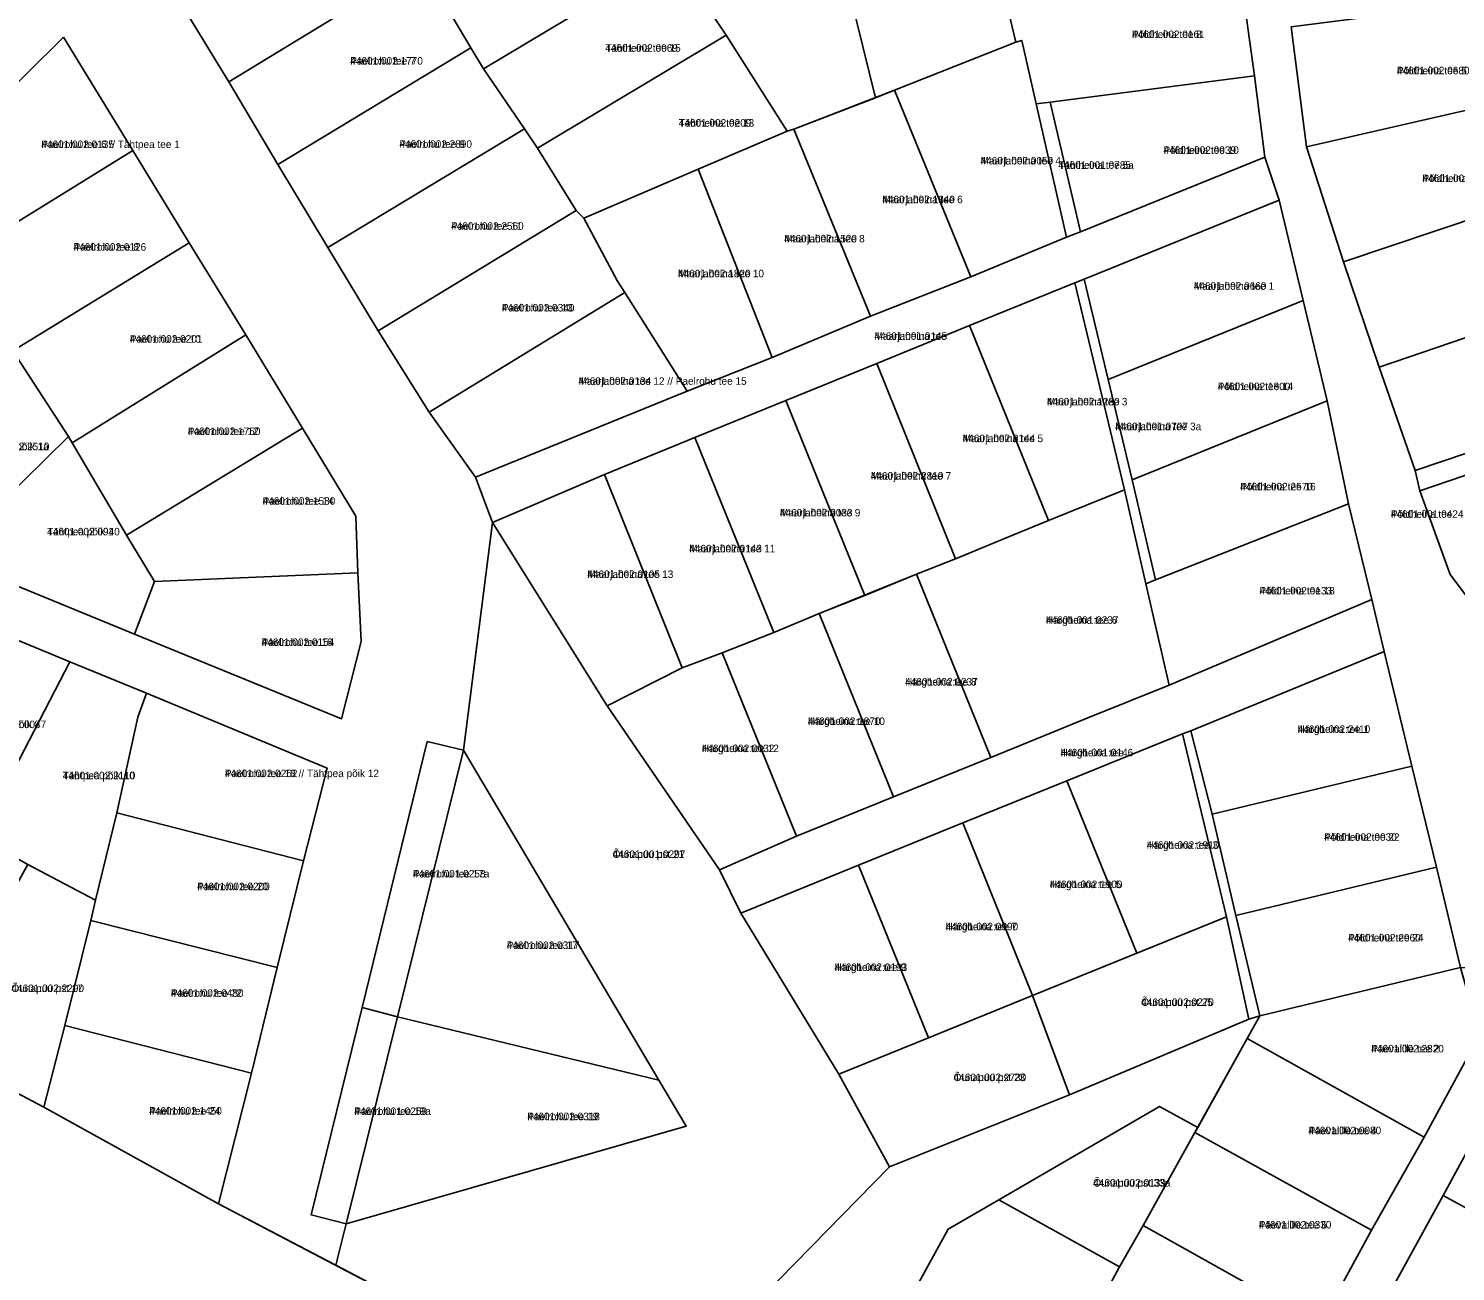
# Model space of a CAD drawing. Extents: x 551843 to 558501, y 6589003 to 6595718.
# Drawn here: x 552375.1 to 552659.9, y 6593483.8 to 6593731.8 of the extents above; entities that cross this region are included whole.
import ezdxf

# ---------------------------------------------------------------- set-up
doc = ezdxf.new("R2010")
doc.units = 0
for name, color, linetype in [('L_AADRESS', 7, 'Continuous'), ('PIIR', 7, 'Continuous'), ('TUNNUS', 7, 'Continuous')]:
    doc.layers.add(name, color=color, linetype=linetype)

msp = doc.modelspace()

# ---------------------------------------------------------------- linework, layer by layer
at = {"layer": 'PIIR'}
for points in [[(552493.73, 6593763), (552503.69, 6593746.35), (552465.93, 6593723.75), (552463.36, 6593727.89), (552455.97, 6593740.4)], [(552415.05, 6593721.12), (552404.98, 6593737.65), (552443.41, 6593761.06), (552446.01, 6593757.04), (552453.48, 6593744.53)], [(552544.13, 6593717.92), (552536.52, 6593748.99), (552565.77, 6593756.12), (552565.86, 6593755.74), (552570.38, 6593736.55), (552572.15, 6593729.03), (552547.97, 6593719.47)], [(552424.83, 6593704.63), (552415.05, 6593721.12), (552453.48, 6593744.53), (552455.97, 6593740.4), (552463.36, 6593727.89)], [(552503.69, 6593746.35), (552514.35, 6593730.44), (552476.69, 6593707.93), (552474.09, 6593711.76), (552465.93, 6593723.75)], [(552572.15, 6593729.03), (552570.38, 6593736.55), (552574.46, 6593737.11), (552616.94, 6593742.99), (552619.81, 6593722.34), (552579.05, 6593717.11), (552576.21, 6593716.75), (552573.34, 6593729.4)], [(552627.12, 6593732.09), (552666.3, 6593737.11), (552668.87, 6593717.03), (552630.18, 6593708.17)], [(552382.03, 6593730.06), (552351.96, 6593700.34), (552354.8, 6593695.88), (552337.85, 6593679.4), (552323.89, 6593665.69), (552305.25, 6593647.4), (552336.12, 6593634.77), (552358.56, 6593626.36), (552396.25, 6593610.93), (552437.54, 6593594.04), (552441.45, 6593609.45), (552440.81, 6593623.15), (552440.38, 6593634.5), (552429.75, 6593652.06), (552418.45, 6593670.64), (552407.17, 6593689.04), (552395.89, 6593707.45)], [(552382.03, 6593730.06), (552395.89, 6593707.45), (552360.87, 6593685.8), (552354.8, 6593695.88), (552351.96, 6593700.34)], [(552476.69, 6593707.93), (552514.35, 6593730.44), (552526.5, 6593711.28), (552508.72, 6593703.69), (552485.91, 6593693.95), (552484.41, 6593695.45)], [(552434.84, 6593688.06), (552424.83, 6593704.63), (552463.36, 6593727.89), (552465.93, 6593723.75), (552474.09, 6593711.76)], [(552573.34, 6593729.4), (552576.07, 6593717.35), (552576.21, 6593716.75), (552582.28, 6593690.17), (552563.19, 6593682.26), (552547.97, 6593719.47), (552572.15, 6593729.03)], [(552619.81, 6593722.34), (552621.88, 6593706.11), (552585.09, 6593691.2), (552579.05, 6593717.11)], [(552543.16, 6593674.39), (552527.83, 6593711.71), (552547.97, 6593719.47), (552563.19, 6593682.26)], [(552576.21, 6593716.75), (552579.05, 6593717.11), (552585.09, 6593691.2), (552582.28, 6593690.17)], [(552630.18, 6593708.17), (552668.87, 6593717.03), (552675.27, 6593697.83), (552637.59, 6593685.25)], [(552444.84, 6593671.49), (552434.84, 6593688.06), (552474.09, 6593711.76), (552476.69, 6593707.93), (552484.41, 6593695.45)], [(552543.16, 6593674.39), (552523.53, 6593666.14), (552508.72, 6593703.69), (552526.5, 6593711.28), (552527.83, 6593711.71)], [(552407.17, 6593689.04), (552371.96, 6593667.45), (552371.01, 6593668.92), (552360.87, 6593685.8), (552395.89, 6593707.45)], [(552467.7, 6593633.22), (552464.3, 6593642.26), (552506.56, 6593659.39), (552523.53, 6593666.14), (552543.16, 6593674.39), (552563.19, 6593682.26), (552582.28, 6593690.17), (552585.09, 6593691.2), (552621.88, 6593706.11), (552624.76, 6593697.55), (552585.83, 6593681.78), (552583.95, 6593681.02), (552562.94, 6593672.52), (552544.4, 6593664.92), (552526.25, 6593657.56), (552508.11, 6593650.2), (552490.05, 6593642.82)], [(552506.56, 6593659.39), (552494.11, 6593679.11), (552492.67, 6593681.34), (552485.91, 6593693.95), (552508.72, 6593703.69), (552523.53, 6593666.14)], [(552624.76, 6593697.55), (552629.55, 6593677.52), (552590.61, 6593661.75), (552585.83, 6593681.78)], [(552644.69, 6593664.18), (552637.59, 6593685.25), (552675.27, 6593697.83), (552682.36, 6593677.03)], [(552484.41, 6593695.45), (552485.91, 6593693.95), (552492.67, 6593681.34), (552494.11, 6593679.11), (552455.04, 6593655.2), (552444.84, 6593671.49)], [(552407.17, 6593689.04), (552418.45, 6593670.64), (552383.81, 6593649.14), (552383.03, 6593650.38), (552371.96, 6593667.45)], [(552590.61, 6593661.75), (552595.4, 6593641.72), (552600.06, 6593621.77), (552598.13, 6593621.01), (552593.83, 6593639.72), (552583.95, 6593681.02), (552585.83, 6593681.78)], [(552494.11, 6593679.11), (552506.56, 6593659.39), (552464.3, 6593642.26), (552455.04, 6593655.2)], [(552583.95, 6593681.02), (552593.83, 6593639.72), (552578.71, 6593633.59), (552562.94, 6593672.52)], [(552590.61, 6593661.75), (552629.55, 6593677.52), (552634.33, 6593657.49), (552595.4, 6593641.72)], [(552651.9, 6593643.62), (552644.69, 6593664.18), (552682.36, 6593677.03), (552689.32, 6593656.23)], [(552429.75, 6593652.06), (552394.61, 6593630.69), (552383.81, 6593649.14), (552418.45, 6593670.64)], [(552562.94, 6593672.52), (552578.71, 6593633.59), (552571.71, 6593630.76), (552560.15, 6593625.97), (552544.4, 6593664.92)], [(552383.03, 6593650.38), (552364.9, 6593632.58), (552358.56, 6593626.36), (552336.12, 6593634.77), (552345.56, 6593644.05), (552359.64, 6593657.88), (552371.01, 6593668.92), (552371.96, 6593667.45)], [(552544.4, 6593664.92), (552560.15, 6593625.97), (552552.33, 6593622.89), (552542.03, 6593618.64), (552526.25, 6593657.56)], [(552526.25, 6593657.56), (552542.03, 6593618.64), (552532.92, 6593615.03), (552523.89, 6593611.28), (552508.11, 6593650.2)], [(552595.4, 6593641.72), (552634.33, 6593657.49), (552638.59, 6593636.95), (552600.06, 6593621.77)], [(552364.9, 6593632.58), (552383.03, 6593650.38), (552383.81, 6593649.14), (552394.61, 6593630.69), (552400.19, 6593621.47), (552396.25, 6593610.93), (552358.56, 6593626.36)], [(552429.75, 6593652.06), (552440.38, 6593634.5), (552440.81, 6593623.15), (552400.19, 6593621.47), (552394.61, 6593630.69)], [(552695.58, 6593640.93), (552697.14, 6593637.51), (552665.39, 6593614.19), (552658.86, 6593622.86), (552652.84, 6593639.55), (552690.68, 6593652.43)], [(552508.11, 6593650.2), (552523.89, 6593611.28), (552513.55, 6593607.18), (552505.53, 6593604.25), (552490.05, 6593642.82)], [(552490.05, 6593642.82), (552505.53, 6593604.25), (552490.58, 6593596.62), (552467.7, 6593633.22)], [(552567.18, 6593586.3), (552552.33, 6593622.89), (552560.15, 6593625.97), (552571.71, 6593630.76), (552578.71, 6593633.59), (552593.83, 6593639.72), (552598.13, 6593621.01), (552602.79, 6593600.76), (552586.55, 6593594.21)], [(552598.13, 6593621.01), (552600.06, 6593621.77), (552638.59, 6593636.95), (552643.21, 6593617.82), (552602.79, 6593600.76)], [(552461.93, 6593587.77), (552467.7, 6593633.22), (552490.58, 6593596.62), (552513.02, 6593563.94), (552517.24, 6593555.3), (552536.83, 6593523.16), (552546.96, 6593504.67), (552496.72, 6593453.35), (552436.41, 6593485.01), (552438.47, 6593493.3), (552506.38, 6593512.78), (552500.93, 6593521.97)], [(552441.45, 6593609.45), (552437.54, 6593594.04), (552396.25, 6593610.93), (552400.19, 6593621.47), (552440.81, 6593623.15)], [(552567.18, 6593586.3), (552547.76, 6593578.47), (552532.92, 6593615.03), (552552.33, 6593622.89)], [(552517.24, 6593555.3), (552513.02, 6593563.94), (552528.37, 6593570.62), (552547.76, 6593578.47), (552567.18, 6593586.3), (552586.55, 6593594.21), (552602.79, 6593600.76), (552643.21, 6593617.82), (552645.72, 6593607.46), (552607.1, 6593591.67), (552605.47, 6593591.05), (552582.37, 6593581.69), (552561.56, 6593573.27), (552540.75, 6593564.84)], [(552383.34, 6593605.44), (552365.17, 6593570.42), (552357.05, 6593574.64), (552357.23, 6593574.95), (552344.87, 6593581.78), (552361.78, 6593614.36)], [(552528.37, 6593570.62), (552513.55, 6593607.18), (552523.89, 6593611.28), (552532.92, 6593615.03), (552547.76, 6593578.47)], [(552398.63, 6593599.15), (552396.89, 6593594.35), (552392.67, 6593575.27), (552388.43, 6593557.86), (552374.95, 6593565.01), (552365.17, 6593570.42), (552383.34, 6593605.44)], [(552505.53, 6593604.25), (552513.55, 6593607.18), (552528.37, 6593570.62), (552513.02, 6593563.94), (552490.58, 6593596.62)], [(552645.72, 6593607.46), (552651.21, 6593584.59), (552611.35, 6593574.99), (552607.1, 6593591.67)], [(552434.72, 6593584.18), (552429.97, 6593565.68), (552392.67, 6593575.27), (552396.89, 6593594.35), (552398.63, 6593599.15)], [(552605.47, 6593591.05), (552614.21, 6593554.53), (552596.32, 6593547.28), (552582.37, 6593581.69)], [(552461.93, 6593587.77), (552448.73, 6593534.61), (552441.67, 6593536.46), (552454.67, 6593589.51)], [(552461.93, 6593587.77), (552500.93, 6593521.97), (552448.73, 6593534.61)], [(552651.21, 6593584.59), (552656.12, 6593564.46), (552616.06, 6593554.82), (552611.35, 6593574.99)], [(552561.56, 6593573.27), (552582.37, 6593581.69), (552596.32, 6593547.28), (552575.52, 6593538.85)], [(552388.43, 6593557.86), (552392.67, 6593575.27), (552429.97, 6593565.68), (552424.68, 6593544.42), (552387.5, 6593553.79)], [(552561.56, 6593573.27), (552575.52, 6593538.85), (552554.71, 6593530.42), (552540.75, 6593564.84)], [(552354.87, 6593528.87), (552374.95, 6593565.01), (552388.43, 6593557.86), (552387.5, 6593553.79), (552382.29, 6593532.84), (552378.15, 6593516.55)], [(552536.83, 6593523.16), (552517.24, 6593555.3), (552540.75, 6593564.84), (552554.71, 6593530.42)], [(552656.12, 6593564.46), (552660.92, 6593544.41), (552620.85, 6593534.78), (552616.06, 6593554.82)], [(552419.61, 6593523.37), (552382.29, 6593532.84), (552387.5, 6593553.79), (552424.68, 6593544.42)], [(552614.21, 6593554.53), (552618.68, 6593534.12), (552582.91, 6593518.99), (552575.52, 6593538.85)], [(552660.92, 6593544.41), (552681.3, 6593543.01), (552676.56, 6593534.11), (552667.17, 6593516.83), (552657.46, 6593498.94), (552647.84, 6593481.41), (552638.03, 6593464.12), (552628.37, 6593446.6), (552618.71, 6593429.08), (552609.04, 6593411.57), (552599.39, 6593394.06), (552591.99, 6593398.44), (552602.33, 6593417.19), (552612.65, 6593435.92), (552622.77, 6593454.66), (552632.95, 6593473.18), (552643.15, 6593492.04), (552653.7, 6593510.58), (552664.72, 6593530.92)], [(552620.85, 6593534.78), (552660.92, 6593544.41), (552664.72, 6593530.92), (552653.7, 6593510.58), (552618.35, 6593530.28)], [(552438.47, 6593493.3), (552431.49, 6593495.08), (552441.67, 6593536.46), (552448.73, 6593534.61)], [(552575.52, 6593538.85), (552582.91, 6593518.99), (552546.96, 6593504.67), (552536.83, 6593523.16), (552554.71, 6593530.42)], [(552448.73, 6593534.61), (552500.93, 6593521.97), (552506.38, 6593512.78), (552438.47, 6593493.3)], [(552412.99, 6593497.3), (552378.15, 6593516.55), (552382.29, 6593532.84), (552419.61, 6593523.37)], [(552653.7, 6593510.58), (552643.15, 6593492.04), (552607.91, 6593511.51), (552618.35, 6593530.28)], [(552608.47, 6593512.52), (552607.91, 6593511.51), (552597.6, 6593492.97), (552592.89, 6593484.72), (552568.76, 6593498.06), (552600.87, 6593516.72)], [(552667.17, 6593516.83), (552704.66, 6593495.87), (552695.23, 6593478.3), (552657.46, 6593498.94)], [(552607.91, 6593511.51), (552643.15, 6593492.04), (552632.95, 6593473.18), (552597.6, 6593492.97)], [(552558.69, 6593492.22), (552568.76, 6593498.06), (552592.89, 6593484.72), (552587.23, 6593474.17), (552580.47, 6593461.92), (552550.96, 6593478.21)], [(552657.46, 6593498.94), (552695.23, 6593478.3), (552685.33, 6593460.85), (552647.84, 6593481.41)], [(552597.6, 6593492.97), (552632.95, 6593473.18), (552622.77, 6593454.66), (552587.23, 6593474.17), (552592.89, 6593484.72)]]:
    msp.add_lwpolyline(points, close=True, dxfattribs=at)
for points in [[(552536.52, 6593748.99), (552544.13, 6593717.92), (552527.83, 6593711.71), (552526.5, 6593711.28), (552514.35, 6593730.44), (552503.69, 6593746.35)], [(552660.92, 6593544.41), (552656.12, 6593564.46), (552651.21, 6593584.59), (552645.72, 6593607.46), (552643.21, 6593617.82), (552638.59, 6593636.95), (552634.33, 6593657.49), (552629.55, 6593677.52), (552624.76, 6593697.55), (552621.88, 6593706.11), (552619.81, 6593722.34), (552616.94, 6593742.99)], [(552404.98, 6593737.65), (552415.05, 6593721.12), (552424.83, 6593704.63), (552434.84, 6593688.06), (552444.84, 6593671.49), (552455.04, 6593655.2), (552464.3, 6593642.26), (552467.7, 6593633.22), (552461.93, 6593587.77), (552454.67, 6593589.51), (552441.67, 6593536.46), (552431.49, 6593495.08), (552438.47, 6593493.3), (552436.41, 6593485.01), (552412.99, 6593497.3), (552419.61, 6593523.37), (552424.68, 6593544.42), (552429.97, 6593565.68), (552434.72, 6593584.18), (552398.63, 6593599.15), (552383.34, 6593605.44), (552361.78, 6593614.36)], [(552627.12, 6593732.09), (552630.18, 6593708.17), (552637.59, 6593685.25), (552644.69, 6593664.18), (552651.9, 6593643.62), (552652.84, 6593639.55), (552658.86, 6593622.86), (552665.39, 6593614.19)], [(552690.68, 6593652.43), (552652.84, 6593639.55), (552651.9, 6593643.62), (552689.32, 6593656.23)], [(552354.87, 6593528.87), (552378.15, 6593516.55), (552412.99, 6593497.3), (552496.72, 6593453.35), (552546.96, 6593504.67), (552582.91, 6593518.99), (552618.68, 6593534.12), (552620.85, 6593534.78), (552618.35, 6593530.28), (552608.47, 6593512.52), (552600.87, 6593516.72), (552568.76, 6593498.06), (552558.69, 6593492.22), (552550.96, 6593478.21)]]:
    msp.add_lwpolyline(points, dxfattribs=at)

# ---------------------------------------------------------------- texts
at = {"layer": 'L_AADRESS'}
for s, p in [('Põldheina tee 8', (552595.36, 6593729.87)), ('Tähtheina tee 15', (552490.21, 6593727.14)), ('Paelrohu tee 7', (552439.3, 6593724.58)), ('Põldheina tee 5', (552648.24, 6593722.64)), ('Tähtheina tee 13', (552504.87, 6593712.2)), ('Paelrohu tee 6 // Tähtpea tee 1', (552377.62, 6593707.93)), ('Paelrohu tee 9', (552449.1, 6593707.98)), ('Põldheina tee 10', (552601.63, 6593706.77)), ('Maarjaheina tee 4', (552565.12, 6593704.66)), ('Tähtheina tee 5a', (552580.65, 6593703.78)), ('Põldheina tee 7', (552653.31, 6593701.14)), ('Maarjaheina tee 6', (552545.51, 6593696.92)), ('Paelrohu tee 11', (552459.42, 6593691.62)), ('Maarjaheina tee 8', (552525.94, 6593689.1)), ('Paelrohu tee 8', (552384.06, 6593687.45)), ('Maarjaheina tee 10', (552504.72, 6593682.14)), ('Maarjaheina tee 1', (552607.69, 6593679.65)), ('Paelrohu tee 13', (552469.55, 6593675.32)), ('Paelrohu tee 10', (552395.29, 6593669.09)), ('Maarjaheina tee', (552543.95, 6593669.66)), ('Maarjaheina tee 12 // Paelrohu tee 15', (552484.87, 6593660.69)), ('Põldheina tee 14', (552612.47, 6593659.62)), ('Maarjaheina tee 3', (552578.38, 6593656.58)), ('Maarjaheina tee 3a', (552592.01, 6593651.63)), ('Paelrohu tee 12', (552406.86, 6593650.67)), ('Maarjaheina tee 5', (552561.55, 6593649.25)), ('Tähtpea põik 1a', (552364.73, 6593647.64)), ('Maarjaheina tee 7', (552543.2, 6593641.78)), ('Põldheina tee 16', (552616.96, 6593639.63)), ('Paelrohu tee 14', (552421.8, 6593636.76)), ('Maarjaheina tee 9', (552525.07, 6593634.43)), ('Põldheina tee', (552647.03, 6593634.15)), ('Tähtpea põik 1', (552378.78, 6593630.65)), ('Maarjaheina tee 11', (552506.97, 6593627.26)), ('Maarjaheina tee 13', (552486.62, 6593622.15)), ('Põldheina tee 18', (552620.79, 6593618.86)), ('Härgheina tee 6', (552578.16, 6593613.01)), ('Paelrohu tee 16', (552421.6, 6593608.59)), ('Härgheina tee 8', (552550.05, 6593600.68)), ('Tähtpea põik 8', (552364.11, 6593592.19)), ('Härgheina tee 10', (552530.65, 6593592.82)), ('Härgheina tee 1', (552628.42, 6593591.23)), ('Härgheina tee 12', (552509.47, 6593587.4)), ('Härgheina tee', (552581.1, 6593586.56)), ('Tähtpea põik 10', (552381.9, 6593581.99)), ('Paelrohu tee 18 // Tähtpea põik 12', (552414.26, 6593582.41)), ('Põldheina tee 22', (552633.71, 6593569.71)), ('Õunapuu pst 21', (552491.68, 6593566.29)), ('Härgheina tee 3', (552598.29, 6593568.11)), ('Paelrohu tee 17a', (552451.8, 6593562.39)), ('Paelrohu tee 20', (552408.72, 6593559.85)), ('Härgheina tee 5', (552578.94, 6593560.27)), ('Härgheina tee 7', (552558.14, 6593551.85)), ('Põldheina tee 24', (552638.49, 6593549.62)), ('Paelrohu tee 17', (552470.53, 6593548.12)), ('Härgheina tee 9', (552535.98, 6593543.73)), ('Õunapuu pst 17', (552371.65, 6593539.53)), ('Paelrohu tee 22', (552403.5, 6593538.58)), ('Õunapuu pst 25', (552597.2, 6593536.76)), ('Päevalille tee 2', (552643.11, 6593527.49)), ('Õunapuu pst 23', (552559.74, 6593521.76)), ('Paelrohu tee 24', (552399.17, 6593515.07)), ('Paelrohu tee 19a', (552440.11, 6593515.01)), ('Paelrohu tee 19', (552474.64, 6593513.96)), ('Päevalille tee 4', (552630.6, 6593511.16)), ('Õunapuu pst 33a', (552587.62, 6593500.72)), ('Päevalille tee 6', (552620.66, 6593492.35))]:
    msp.add_text(s, height=1.5, dxfattribs=at).set_placement(p)
at = {"layer": 'TUNNUS'}
for s, p in [('44601:002:0161', (552595.36, 6593729.87)), ('44601:002:0069', (552490.21, 6593727.14)), ('44601:002:1770', (552439.3, 6593724.58)), ('44601:002:0680', (552648.24, 6593722.64)), ('44601:002:0209', (552504.87, 6593712.2)), ('44601:002:0135', (552377.62, 6593707.93)), ('44601:002:2890', (552449.1, 6593707.98)), ('44601:002:0039', (552601.63, 6593706.77)), ('44601:002:0050', (552565.12, 6593704.66)), ('44601:001:0785', (552580.65, 6593703.78)), ('44601:002:1780', (552653.31, 6593701.14)), ('44601:002:1840', (552545.51, 6593696.92)), ('44601:002:2560', (552459.42, 6593691.62)), ('44601:002:1520', (552525.94, 6593689.1)), ('44601:002:0126', (552384.06, 6593687.45)), ('44601:002:1820', (552504.72, 6593682.14)), ('44601:002:0660', (552607.69, 6593679.65)), ('44601:002:0340', (552469.55, 6593675.32)), ('44601:002:0201', (552395.29, 6593669.09)), ('44601:001:0145', (552543.95, 6593669.66)), ('44601:002:0134', (552484.87, 6593660.69)), ('44601:002:1800', (552612.47, 6593659.62)), ('44601:002:1280', (552578.38, 6593656.58)), ('44601:001:0707', (552592.01, 6593651.63)), ('44601:002:1750', (552406.86, 6593650.67)), ('44601:002:0144', (552561.55, 6593649.25)), ('44601:002:2510', (552364.73, 6593647.64)), ('44601:002:2810', (552543.2, 6593641.78)), ('44601:002:2570', (552616.96, 6593639.63)), ('44601:002:1580', (552421.8, 6593636.76)), ('44601:002:0033', (552525.07, 6593634.43)), ('44601:001:0424', (552647.03, 6593634.15)), ('44601:002:0940', (552378.78, 6593630.65)), ('44601:002:0143', (552506.97, 6593627.26)), ('44601:002:0105', (552486.62, 6593622.15)), ('44601:002:0133', (552620.79, 6593618.86)), ('44601:001:0237', (552578.16, 6593613.01)), ('44601:002:0154', (552421.6, 6593608.59)), ('44601:002:0237', (552550.05, 6593600.68)), ('44601:002:0047', (552364.11, 6593592.19)), ('44601:002:1870', (552530.65, 6593592.82)), ('44601:002:2410', (552628.42, 6593591.23)), ('44601:002:0032', (552509.47, 6593587.4)), ('44601:001:0146', (552581.1, 6593586.56)), ('44601:002:2110', (552381.9, 6593581.99)), ('44601:002:0262', (552414.26, 6593582.41)), ('44601:002:0030', (552633.71, 6593569.71)), ('44601:001:0297', (552491.68, 6593566.29)), ('44601:002:1910', (552598.29, 6593568.11)), ('44601:001:0258', (552451.8, 6593562.39)), ('44601:002:0200', (552408.72, 6593559.85)), ('44601:002:1900', (552578.94, 6593560.27)), ('44601:002:0990', (552558.14, 6593551.85)), ('44601:002:2960', (552638.49, 6593549.62)), ('44601:002:0317', (552470.53, 6593548.12)), ('44601:002:0193', (552535.98, 6593543.73)), ('44601:002:2290', (552371.65, 6593539.53)), ('44601:002:0480', (552403.5, 6593538.58)), ('44601:002:0270', (552597.2, 6593536.76)), ('44601:002:2820', (552643.11, 6593527.49)), ('44601:002:2730', (552559.74, 6593521.76)), ('44601:002:1450', (552399.17, 6593515.07)), ('44601:001:0259', (552440.11, 6593515.01)), ('44601:002:0318', (552474.64, 6593513.96)), ('44601:002:0080', (552630.6, 6593511.16)), ('44601:002:0139', (552587.62, 6593500.72)), ('44601:002:0330', (552620.66, 6593492.35))]:
    msp.add_text(s, height=1.5, dxfattribs=at).set_placement(p)

doc.saveas('drawing.dxf')
